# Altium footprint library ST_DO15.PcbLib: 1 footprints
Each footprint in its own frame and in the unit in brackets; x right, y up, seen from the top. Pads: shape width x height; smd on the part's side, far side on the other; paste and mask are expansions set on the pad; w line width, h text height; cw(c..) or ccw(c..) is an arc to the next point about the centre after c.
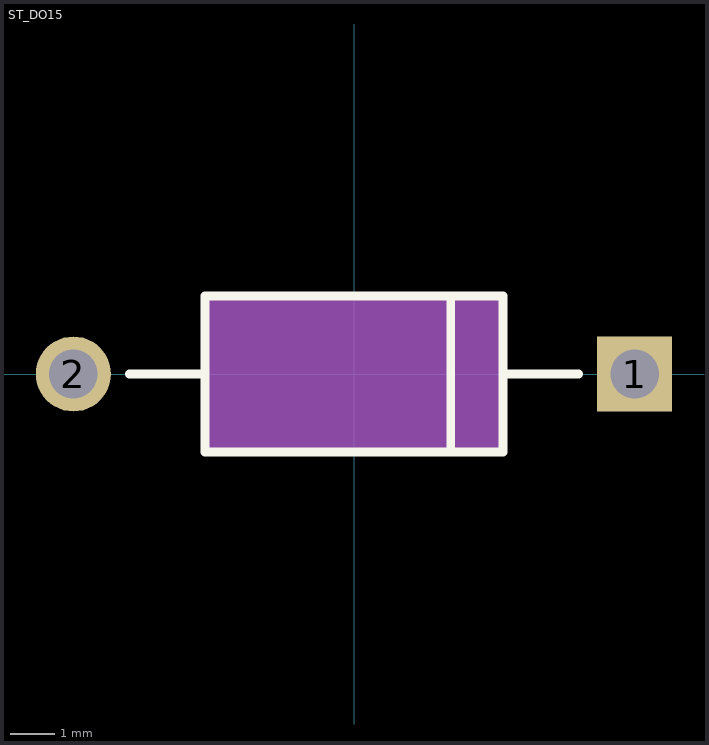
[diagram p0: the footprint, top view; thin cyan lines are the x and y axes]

## ST_DO15 [mm]
pads (2):
  rect 1.7x1.7 hole 1.1: 1(6.35,0)
  round 1.7 hole 1.1: 2(-6.35,0)
Top Overlay:
  lines w0.2: -5.08,0 -3.434,0 ; 2.188,-1.727 2.188,1.765 ; 3.375,0 5.08,0 ; -3.375,-1.765 3.375,-1.765 3.375,1.765 -3.375,1.765 -3.375,-1.765
3D Top (Mech13):
  rectangle: -3.375,-1.765 3.375,1.765
3D body: height 3.53, standoff 0, extent -2.921,1.016 -2.921,1.016
3D body "DO15.step": height 3.52, standoff 0.01, extent -3.411,-1.76 3.339,1.76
